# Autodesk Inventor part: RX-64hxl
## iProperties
Created: 2009-01
Part Number: RX-64hxl
Material: Aluminum-6061
Document SubType Name: Sheet Metal
Designer: Administrator
Density: 1 g/cm^3
Author: Administrator
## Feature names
1. Hole1
2. Corner Round1
3. Hole3
4. Plate1
5. Plate2
6. Bend1
7. Cut1
8. Cut2
9. Cut3
10. Cut4
11. Cut6
